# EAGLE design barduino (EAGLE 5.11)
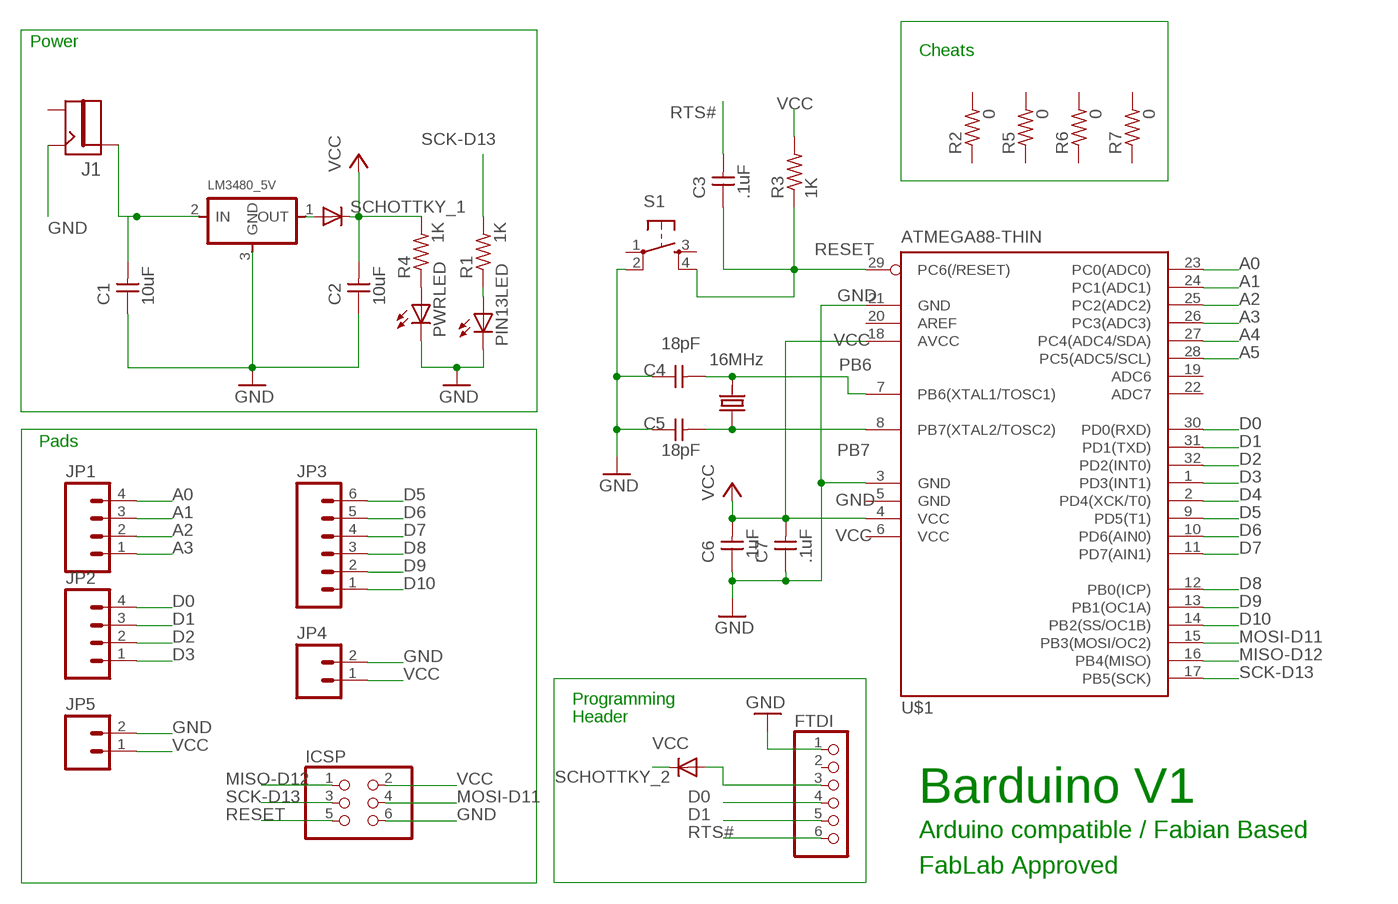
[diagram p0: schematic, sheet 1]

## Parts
C1  10uF  UNPOLARIZED_CAPACITOR1206  [1206]
C2  10uF  UNPOLARIZED_CAPACITOR1206  [1206]
C3  .1uF  UNPOLARIZED_CAPACITOR1206  [1206]
C4  18pF  UNPOLARIZED_CAPACITOR1206  [1206]
C5  18pF  UNPOLARIZED_CAPACITOR1206  [1206]
C6  .1uF  UNPOLARIZED_CAPACITOR1206  [1206]
C7  .1uF  UNPOLARIZED_CAPACITOR1206  [1206]
FTDI  PINHD-1X6  [1X06]
ICSP  PINHD-2X3-SMD  [2X03SMD]
J1  JACK.65MM  [JACK_.65MM]
JP1  M04PTH  [1X04]
JP2  M04PTH  [1X04]
JP3  M06LOCK  [1X06_LOCK]
JP4  M02LOCK  [1X02_LOCK]
JP5  M02LOCK  [1X02_LOCK]
LM3480_5V  REGULATORSOT23  [SOT23]
PIN13LED  LED1206  [1206]
PWRLED  LED1206  [1206]
Q2  16MHz  CRYSTALCS10  [CS10]
R1  1K  RESISTOR1206  [1206]
R2  0  RESISTOR1206  [1206]
R3  1K  RESISTOR1206  [1206]
R4  1K  RESISTOR1206  [1206]
R5  0  RESISTOR1206  [1206]
R6  0  RESISTOR1206  [1206]
R7  0  RESISTOR1206  [1206]
S1  6MM_SWITCH6MM_SWITCH  [6MM_SWITCH]
SCHOTTKY_1  DIODESOD123  [SOD123]
SCHOTTKY_2  DIODESOD123  [SOD123]
U$1  ATMEGA88-THIN  [TQFP32-08THIN]

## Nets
A0: JP1.4 U$1.23(PC0(ADC0))
A1: JP1.3 U$1.24(PC1(ADC1))
A2: JP1.2 U$1.25(PC2(ADC2))
A3: JP1.1 U$1.26(PC3(ADC3))
A4: U$1.27(PC4(ADC4/SDA))
A5: U$1.28(PC5(ADC5/SCL))
CONNECT [power]: FTDI.3 SCHOTTKY_2.ANODE(A)
D0: FTDI.4 JP2.4 U$1.30(PD0(RXD))
D1: FTDI.5 JP2.3 U$1.31(PD1(TXD))
D2: JP2.2 U$1.32(PD2(INT0))
D3: JP2.1 U$1.1(PD3(INT1))
D4: U$1.2(PD4(XCK/T0))
D5: JP3.6 U$1.9(PD5(T1))
D6: JP3.5 U$1.10(PD6(AIN0))
D7: JP3.4 U$1.11(PD7(AIN1))
D8: JP3.3 U$1.12(PB0(ICP))
D9: JP3.2 U$1.13(PB1(OC1A))
D10: JP3.1 U$1.14(PB2(SS/OC1B))
GND [power]: C1.1 C2.1 C4.1 C5.1 C6.1 C7.1 FTDI.1 ICSP.6 J1.CONTACT JP4.2 JP5.2 LM3480_5V.3(GND) PIN13LED.2(C) PWRLED.2(C) S1.2(P1) U$1.3(GND) U$1.21(GND)
MISO-D12: ICSP.1 U$1.16(PB4(MISO))
MOSI-D11: ICSP.4 U$1.15(PB3(MOSI/OC2))
N$1 [power]: LM3480_5V.1(OUT) SCHOTTKY_1.ANODE(A)
N$2: PWRLED.1(A) R4.1
N$3: C1.2 J1.PIN LM3480_5V.2(IN)
N$4: PIN13LED.1(A) R1.1
PB6: C4.2 Q2.P$2 U$1.7(PB6(XTAL1/TOSC1))
PB7: C5.2 Q2.P$1 U$1.8(PB7(XTAL2/TOSC2))
RESET: C3.1 ICSP.5 R3.1 S1.4(S1) U$1.29(PC6(/RESET))
RTS#: C3.2 FTDI.6
SCK-D13: ICSP.3 R1.2 U$1.17(PB5(SCK))
VCC [power]: C2.2 C6.2 C7.2 ICSP.2 JP4.1 JP5.1 R3.2 R4.2 SCHOTTKY_1.CATHODE(C) SCHOTTKY_2.CATHODE(C) U$1.4(VCC) U$1.18(AVCC)
Unconnected: FTDI.2 J1.SHUNT R2.1 R2.2 R5.1 R5.2 R6.1 R6.2 R7.1 R7.2 S1.1(P) S1.3(S) U$1.19(ADC6) U$1.20(AREF) U$1.22(ADC7)

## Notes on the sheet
- Power
- Cheats
- Pads
- Programming
- Header
- Barduino V1
- Arduino compatible / Fabian Based
- FabLab Approved

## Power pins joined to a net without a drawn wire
GND: U$1.5(GND)
VCC: U$1.6(VCC)

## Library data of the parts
C1-C7 = ng:UNPOLARIZED_CAPACITOR: unpolarized_capacitor
FTDI = pinhead:PINHD-1X6: PIN HEADER
ICSP = fab:PINHD-2X3-SMD: PIN HEADER
J1 = ng:JACK
JP1 JP2 = SparkFun:M04: Header 4 Standard 4-pin 0.1" header. Use with straight break away headers (SKU : PRT-00116), right angle break away headers (PRT-00553), swiss pins (PRT-00743), machine pins (PRT-00117), and female headers (PRT-00115). Molex polarized connector foot print use with SKU : PRT-08231 with associated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
JP3 = SparkFun:M06: Header 6 Standard 6-pin 0.1" header. Use with straight break away headers (SKU : PRT-00116), right angle break away headers (PRT-00553), swiss pins (PRT-00743), machine pins (PRT-00117), and female headers (PRT-00115). Molex polarized connector foot print use with SKU : PRT-08094 with associated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
JP4 JP5 = SparkFun:M02: Header 2
LM3480_5V = ng:REGULATOR
PIN13LED PWRLED = ng:LED
Q2 = ng:CRYSTAL: CRYSTAL
R1-R7 = ng:RESISTOR
S1 = ng:6MM_SWITCH: OMRON SWITCH
SCHOTTKY_1 SCHOTTKY_2 = 01_ng:DIODE: DIODE
U$1 = fab:ATMEGA88-THIN

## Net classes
0 default: width 0.635 mm, clearance 0.406 mm
1 power: width 0.635 mm, clearance 0.406 mm

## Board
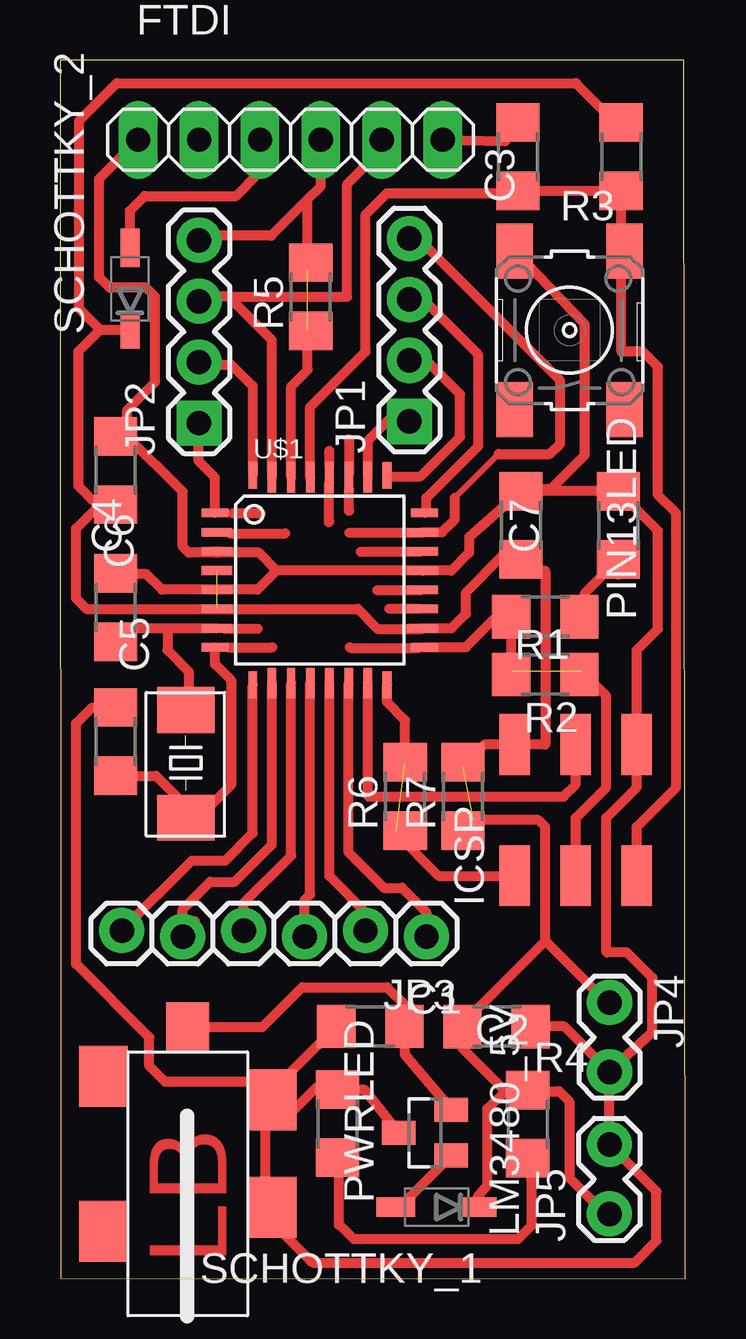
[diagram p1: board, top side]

Size 26.06 x 50.79 mm. Coordinates in mm from the lower left corner, seen from the top.
Outline: 0.03,0.01 26.06,0 26,50.79 0,50.79 0.03,0.01
Copper layers (1*16): Top 0.035mm / dielectric 1.5mm / Bottom 0.035mm
Design rules "default *": minimum track width 10mil, minimum drill 24mil, track to track 8mil, track to pad 8mil, pad to pad 8mil, via to via 8mil, smd to smd 8mil, copper to edge 40mil, drill to drill 8mil, minimum pad ring 12mil, minimum via ring 8mil, stop-mask expansion 4mil, vias tented up to drill 0mil, thermal gap 10mil

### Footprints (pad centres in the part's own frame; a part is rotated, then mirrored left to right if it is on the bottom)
1206 = smd 1.6 x 1.803: 1 -1.422,0; 2 1.422,0
1X06 = drill 1.016 long: 1 -6.35,0; 2 -3.81,0; 3 -1.27,0; 4 1.27,0; 5 3.81,0; 6 6.35,0
2X03SMD = smd 2.54 x 1.27: 1 -2.54,2.54; 2 2.92,2.54; 3 -2.54,0; 4 2.92,0; 5 -2.54,-2.54; 6 2.92,-2.54
JACK_.65MM = smd 2.032 x 2.54: CONTACT 3.578,4.026; SHIELD -3.45,-1.448; SHIELD1 3.578,-0.447; SHUNT -3.45,5.005 | smd 1.778 x 2.032: PIN 0.064,7.071
1X04 = drill 1.016 pad 1.88 square: 1 0,0 | drill 1.016 pad 1.88 round: 2 2.54,0; 3 5.08,0; 4 7.62,0
1X06_LOCK = drill 1.016 pad 1.88 round: 1 0,0; 2 2.54,-0.254; 3 5.08,0; 4 7.62,-0.254; 5 10.16,0; 6 12.7,-0.254
1X02_LOCK = drill 1.016 pad 1.88 round: 1 -0.178,0; 2 2.718,0
SOT23 = smd 1 x 1.4: 1 -0.95,-1.1; 2 0.95,-1.1; 3 0,1.1
CS10 = smd 1.905 x 2.388: P$1 -2.286,0; P$2 2.21,0
6MM_SWITCH = smd 2.286 x 1.524: 1 -3.302,2.286; 2 3.302,2.286; 3 -3.302,-2.286; 4 3.302,-2.286
SOD123 = smd 1.6 x 0.8: ANODE 1.7,0; CATHODE -1.7,0
TQFP32-08THIN = smd 1.118 x 0.356: 1 -4.369,2.8; 8 -4.369,-2.8; 17 4.369,-2.8; 24 4.369,2.8 | smd 1.27 x 0.356: 2 -4.293,2; 3 -4.293,1.2; 4 -4.293,0.4; 5 -4.293,-0.4; 6 -4.293,-1.2; 7 -4.293,-2; 18 4.293,-2; 19 4.293,-1.2; 20 4.293,-0.4; 21 4.293,0.4; 22 4.293,1.2; 23 4.293,2 | smd 0.356 x 1.118: 9 -2.8,-4.369; 16 2.8,-4.369; 25 2.8,4.369; 32 -2.8,4.369 | smd 0.356 x 1.27: 10 -2,-4.293; 14 1.2,-4.293; 15 2,-4.293; 26 2,4.293; 27 1.2,4.293; 31 -2,4.293 | smd 0.35 x 1.27: 11 -1.2,-4.293; 12 -0.4,-4.293; 13 0.4,-4.293; 28 0.4,4.293; 29 -0.4,4.293; 30 -1.2,4.293

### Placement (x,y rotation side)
C1  12.94,10.51 0 top
C2  18.2,10.5 180 top
C3  19.09,46.76 90 top
C4  2.33,27.97 270 top
C5  2.33,22.38 270 top
C6  2.33,33.68 270 top
C7  19.22,31.4 270 top
FTDI  9.61,47.47 0 top
ICSP  21.5,19.33 90 top
J1  5.26,3.42 0 top
JP1  14.57,35.73 90 top
JP2  5.8,35.66 90 top
JP3  15.28,14.25 180 top
JP4  22.92,11.33 270 top
JP5  22.91,2.87 90 top
LM3480_5V  15.22,6.08 90 top
PIN13LED  23.28,31.4 90 top
PWRLED  11.57,6.46 90 top
Q2  5.25,21.49 90 top
R1  20.23,27.59 180 top
R2  20.23,25.17 180 top
R3  23.4,46.76 90 top
R4  19.5,6.44 90 top
R5  10.45,40.92 90 top
R6  14.39,20.09 90 top
R7  16.8,20.09 90 top
S1  21.25,39.53 90 top
SCHOTTKY_1  15.71,2.98 180 top
SCHOTTKY_2  2.92,41.25 90 top
U$1  10.84,29.11 0 top

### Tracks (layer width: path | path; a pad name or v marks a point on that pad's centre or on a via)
A0
  Top 0.254: 16.47,32.55 18.29,34.37
  Top 0.406: U$1.23 15.93,31.11 16.47,31.65 16.47,32.55 | JP1.4 14.82,43.46 20.86,37.42 20.86,34.79 20.44,34.37 18.29,34.37
A1
  Top 0.406: JP1.3 15.03,40.92 17.44,38.51 17.44,34.7 15.28,32.54 15.28,31.99 U$1.24
A2
  Top 0.406: JP1.2 15.15,38.38 16.68,36.86 16.68,35.08 15.03,33.43 13.69,33.43 U$1.25
A3
  Top 0.406: U$1.26 12.84,34.92 13.76,35.84 JP1.1
CONNECT
  Top 0.406: 8.32,47.49 FTDI.3 8.31,47.44 8.31,46.09 7.34,45.12 3.52,45.12 2.92,44.52 SCHOTTKY_2.ANODE
D0  (1 unrouted)
  Top 0.406: U$1.30 9.64,37.18 10.33,37.87 10.33,39.52 | 10.33,44.99 8.8,43.46 6.1,43.46 JP2.4 | 10.33,42.06 10.33,44.99 | 10.33,44.99 10.88,45.53 FTDI.4
D1
  Top 0.406: U$1.31 8.84,39.11 7.03,40.92 | 7.03,40.92 11.98,40.92 11.98,45.62 12.87,46.51 FTDI.5 | 7.03,40.92 6.1,40.92 JP2.3
D2
  Top 0.406: U$1.32 8.04,37.2 7.13,38.1 5.83,38.1 JP2.2
D3
  Top 0.406: U$1.1 6.47,33.39 5.79,34.07 5.79,35.82 JP2.1
D5
  Top 0.406: U$1.9 8.04,18.56 6.9,17.43 5.5,17.43 JP3.6
D6
  Top 0.406: U$1.10 8.84,18.09 7.28,16.54 6.26,16.54 5.12,15.39 JP3.5 5.63,14.89
D7
  Top 0.406: U$1.11 9.64,17.62 7.66,15.65 JP3.4
D8
  Top 0.406: U$1.12 10.44,16.01 10.2,15.78 JP3.3
D9
  Top 0.406: U$1.13 11.24,16.77 12.87,15.14 12.87,14.63 JP3.2
D10
  Top 0.406: U$1.14 12.04,17.75 13.5,16.28 14.26,16.28 15.28,15.27 JP3.1
GND
  Top 0.406: C7.1 PIN13LED.2 24.93,31.17 24.93,27.08 24.04,26.19 ICSP.6 | ICSP.6 24.04,21.36 | C4.1 2.35,29.36 3.6,29.36 4.25,28.71 U$1.5 8.24,28.71 9.04,29.51 | 9.04,29.51 U$1.21 16.32,29.51 17.06,30.25 17.06,30.91 C7.1 | 9.04,29.51 8.3,30.25 6.6,30.25 U$1.3 6.49,30.25 5.37,30.25 5.12,30.51 5.12,32.79 2.81,35.1 | 2.81,35.1 C6.1 | C5.1 1.34,23.8 0.68,23.14 0.68,13.11 3.72,10.06 3.72,8.86 4.37,8.22 8.06,8.22 J1.CONTACT | J1.CONTACT 8.91,6.76 | C7.1 20.51,32.95 21.88,34.32 21.88,39.78 S1.2 | ICSP.6 24.04,20.47 22.77,19.2 22.77,13.62 22.8,13.59 23.64,13.59 24.7,12.53 24.7,10.29 24.42,10.02 24.42,10.01 JP4.2 | JP5.2 JP4.2 | JP5.2 22.41,5.27 | 8.91,6.76 8.55,6.39 8.55,2.64 10.25,0.94 10.26,0.94 10.54,0.66 23.96,0.66 24.87,1.57 24.87,3.63 JP5.2 | 8.91,6.76 9.49,6.76 10.7,7.97 11.48,7.97 PWRLED.2 12.69,7.88 LM3480_5V.3 | J1.CONTACT 8.84,7.83 C1.1 | C2.1 21.02,10.5 JP4.2 | 2.81,35.1 2.81,36.21 3.96,37.36 3.96,40.93 3.6,41.29 2.08,41.29 1.63,41.74 1.63,45.84 FTDI.1
MISO-D12  (1 unrouted)
  Top 0.406: ICSP.1 15.79,16.79 14.01,18.57 | U$1.16 13.64,24.02 14.39,23.27 14.39,21.49
MOSI-D11
  Top 0.406: U$1.15 12.84,20.13 12.87,20.09 21,20.09 21.5,20.6 ICSP.4
N$1
  Top 0.406: SCHOTTKY_1.ANODE 14.45,2.89 14.45,3.26 LM3480_5V.1
N$2
  Top 0.406: 19.68,3.84 R4.1 19.68,4.83 19.68,2.22 19.11,1.65 12.25,1.65 11.66,2.24 11.63,2.24 11.63,4.98 PWRLED.1
N$3
  Top 0.406: J1.PIN 8.44,10.49 10.1,12.14 13.64,12.14 14.4,11.39 14.4,10.54 C1.2 14.37,9.35 LM3480_5V.2
N$4
  Top 0.406: 23.28,29.34 PIN13LED.1 21.91,28.6 R1.1
N$6
  Top 0.406: 15.03,28.7 13.24,28.7 13.23,28.68
N$7
  Top 0.406: 14.98,27.91 13.74,27.91
N$11
  Top 0.406: 12.55,30.29 15.02,30.29
N$12
  Top 0.406: 12.07,31.09 15.09,31.09
N$13
  Top 0.406: 12.05,32.88 12.05,32.01 12.04,32
N$14
  Top 0.406: 11.22,33.16 11.22,31.54 11.21,31.53
N$15
  Top 0.406: 12.06,33.55 12.06,34.96 12.04,34.98
N$16
  Top 0.406: 11.23,33.87 11.23,34.5
N$17
  Top 0.406: 6.87,27.09 8.26,27.09
N$18
  Top 0.406: 7.01,26.31 8.85,26.31
N$19
  Top 0.406: 7.08,31.06 9.4,31.06
N$20
  Top 0.406: 7.21,31.9 8.38,31.9
N$21
  Top 0.406: 14.97,26.29 12.11,26.29 12.09,26.3
PB6
  Top 0.406: 4.49,27.11 2.89,27.11 C4.2 | 4.49,27.11 U$1.7 | 4.49,27.11 4.49,26.19 5.37,25.3 5.37,23.83 Q2.P$2
PB7
  Top 0.406: U$1.8 6.47,25.61 7.15,24.92 7.15,20.6 5.76,19.2 | 5.76,19.2 Q2.P$1 | C5.2 4,20.96 5.76,19.2
RESET
  Top 0.406: U$1.29 10.44,36.33 12.74,38.64 12.74,44.35 13.63,45.24 18.94,45.24 C3.1 R3.1 23.4,42.7 23.28,42.7 S1.4 23.41,42.7 23.41,38.64 24.3,38.64 24.93,38 24.93,32.67 25.69,31.9 25.69,20.47 24.04,18.82 ICSP.5
RTS#
  Top 0.406: FTDI.6 18.56,47.4 C3.2
SCK-D13  (1 unrouted)
  Top 0.406: U$1.17 16.93,26.32 18.46,27.84 R1.2 18.81,25.33 18.84,25.3 | ICSP.3 21.5,19.2 22.77,20.47 22.77,24.28 21.76,25.3
VCC  (2 unrouted)
  Top 0.406: 1.82,32.41 0.68,31.27 0.68,28.35 1.11,27.91 U$1.6 12.42,27.91 13.25,27.08 15.1,27.08 U$1.18 16.33,27.11 16.93,27.71 16.93,28.6 18.46,30.13 19.07,30.13 C7.2 20.23,29.49 20.23,22.25 ICSP.2 17.69,22.25 16.8,21.36 | 1.82,32.41 2.17,32.41 C6.2 | JP4.1 22.36,11.95 20.37,13.94 20.37,13.95 20.28,14.04 | 20.28,14.04 | 20.24,14.08 20.28,14.04 | 20.24,14.08 20.24,18.82 19.95,19.11 17.24,19.11 16.8,18.67 | 20.24,14.08 16.78,10.63 C2.2 16.78,9.59 18.57,7.8 | 18.57,7.8 19.45,7.8 R4.2 | 20.23,7.88 19.52,7.88 R4.2 | JP5.1 22.75,2.69 21.23,4.21 21.23,7.4 20.82,7.81 19.55,7.81 R4.2 | SCHOTTKY_1.CATHODE 17.41,3.39 17.81,3.88 17.81,7.07 18.57,7.8 | 1.67,39.55 0.79,40.43 0.79,48.25 2.36,49.82 21.52,49.82 23.15,48.19 R3.2 | 1.67,39.55 SCHOTTKY_2.CATHODE | 1.82,32.41 1.39,32.41 0.77,33.04 0.77,38.66 1.67,39.55

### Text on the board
Top: LB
